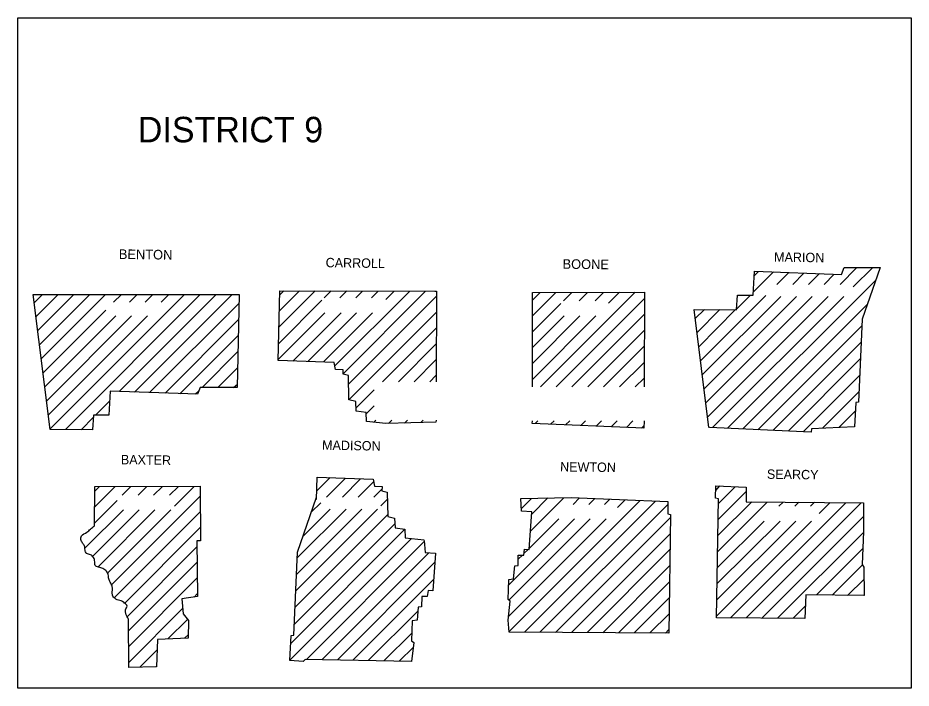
# Model space of a CAD drawing. Extents: x 23481 to 28196, y 1325020 to 1327623.
# Drawn here: x 27385.4 to 27785.4, y 1325389.9 to 1325689.9 of the extents above; entities that cross this region are included whole.
import ezdxf

# ---------------------------------------------------------------- set-up
doc = ezdxf.new("R2010")
doc.units = 0
doc.layers.add('S_ELECTRIC_UTILITIES_ANNOT', color=7, linetype='Continuous')

msp = doc.modelspace()

# ---------------------------------------------------------------- linework, layer by layer
at = {"layer": 'S_ELECTRIC_UTILITIES_ANNOT'}
msp.add_lwpolyline([(27385.36, 1325389.92), (27385.36, 1325689.92), (27785.36, 1325689.92), (27785.36, 1325389.92)], close=True, dxfattribs=at)
for points in [[(27688.46, 1325559.32), (27707.16, 1325559.22), (27707.66, 1325565.82), (27714.56, 1325565.82), (27715.16, 1325576.52), (27754.16, 1325575.12), (27755.36, 1325578.12), (27771.46, 1325578.22), (27763.36, 1325555.02), (27761.76, 1325517.92), (27760.56, 1325517.82), (27759.96, 1325506.92)], [(27714.66, 1325567.12), (27723.66, 1325576.22)], [(27715.06, 1325574.52), (27716.96, 1325576.42)], [(27753.56, 1325570.62), (27761.06, 1325578.12)], [(27759.46, 1325569.52), (27768.16, 1325578.12)], [(27703.16, 1325506.22), (27769.36, 1325572.32)], [(27725.26, 1325570.62), (27730.56, 1325575.92)], [(27732.36, 1325570.62), (27737.36, 1325575.72)], [(27739.36, 1325570.62), (27744.26, 1325575.52)], [(27746.46, 1325570.62), (27750.96, 1325575.22)], [(27399.76, 1325505.62), (27392.16, 1325566.12)], [(27392.16, 1325566.12), (27484.46, 1325566.12)], [(27392.66, 1325562.42), (27396.46, 1325566.12)], [(27393.46, 1325556.12), (27403.46, 1325566.12)], [(27394.26, 1325549.92), (27410.46, 1325566.12)], [(27395.06, 1325543.62), (27417.56, 1325566.12)], [(27395.86, 1325537.32), (27424.66, 1325566.12)], [(27399.86, 1325505.92), (27459.96, 1325566.12)], [(27406.66, 1325505.62), (27467.06, 1325566.12)], [(27428.26, 1325562.62), (27431.76, 1325566.12)], [(27430.76, 1325522.62), (27474.16, 1325566.12)], [(27435.36, 1325562.62), (27438.76, 1325566.12)], [(27437.56, 1325522.42), (27481.26, 1325566.12)], [(27442.36, 1325562.62), (27445.86, 1325566.12)], [(27449.46, 1325562.62), (27452.96, 1325566.12)], [(27484.46, 1325566.12), (27483.56, 1325524.52)], [(27501.96, 1325536.52), (27502.66, 1325567.72)], [(27502.26, 1325551.42), (27518.56, 1325567.72)], [(27502.46, 1325558.72), (27511.46, 1325567.72)], [(27502.66, 1325565.92), (27504.46, 1325567.72)], [(27502.66, 1325567.72), (27572.06, 1325567.62), (27572.76, 1325567.62)], [(27522.56, 1325564.62), (27525.66, 1325567.72)], [(27527.36, 1325534.12), (27560.86, 1325567.62)], [(27529.56, 1325564.62), (27532.66, 1325567.72)], [(27530.96, 1325530.62), (27567.96, 1325567.62)], [(27533.46, 1325526.02), (27572.76, 1325565.32)], [(27536.76, 1325564.62), (27539.66, 1325567.62)], [(27543.76, 1325564.62), (27546.76, 1325567.62)], [(27550.16, 1325563.92), (27553.86, 1325567.62)], [(27572.76, 1325567.62), (27572.66, 1325527.02)], [(27615.76, 1325563.52), (27619.26, 1325567.02)], [(27615.76, 1325524.72), (27615.86, 1325567.02)], [(27615.86, 1325567.02), (27665.96, 1325567.22)], [(27615.86, 1325556.52), (27626.26, 1325567.02)], [(27619.36, 1325524.72), (27661.76, 1325567.12)], [(27626.46, 1325524.72), (27665.86, 1325564.12)], [(27629.76, 1325563.32), (27633.46, 1325567.02)], [(27636.76, 1325563.32), (27640.46, 1325567.02)], [(27643.86, 1325563.32), (27647.56, 1325567.02)], [(27649.86, 1325562.22), (27654.76, 1325567.12)], [(27665.96, 1325567.22), (27665.76, 1325524.72)], [(27691.06, 1325536.42), (27720.36, 1325565.72)], [(27691.86, 1325530.12), (27726.96, 1325565.22)], [(27692.66, 1325523.92), (27733.96, 1325565.22)], [(27693.46, 1325517.62), (27741.06, 1325565.22)], [(27694.26, 1325511.32), (27748.16, 1325565.22)], [(27696.46, 1325506.52), (27755.26, 1325565.22)], [(27707.26, 1325559.72), (27713.36, 1325565.82)], [(27444.36, 1325522.22), (27484.36, 1325562.12)], [(27502.16, 1325544.22), (27521.46, 1325563.52)], [(27615.86, 1325549.42), (27628.46, 1325562.02)], [(27709.96, 1325505.92), (27765.56, 1325561.52)], [(27396.66, 1325531.02), (27424.76, 1325559.12)], [(27397.46, 1325524.72), (27429.26, 1325556.52)], [(27398.26, 1325518.52), (27436.26, 1325556.52)], [(27399.06, 1325512.22), (27443.36, 1325556.52)], [(27501.96, 1325537.02), (27522.86, 1325557.92)], [(27508.46, 1325536.32), (27530.06, 1325557.92)], [(27515.26, 1325536.12), (27537.06, 1325557.92)], [(27522.16, 1325535.92), (27544.16, 1325557.92)], [(27533.56, 1325519.02), (27572.76, 1325558.22)], [(27615.76, 1325528.12), (27644.16, 1325556.52)], [(27615.76, 1325535.22), (27637.06, 1325556.52)], [(27615.86, 1325542.42), (27629.96, 1325556.52)], [(27633.46, 1325524.72), (27665.86, 1325557.12)], [(27694.76, 1325506.52), (27688.16, 1325559.32)], [(27688.66, 1325555.32), (27692.76, 1325559.32)], [(27689.46, 1325549.02), (27699.76, 1325559.32)], [(27690.26, 1325542.72), (27706.76, 1325559.32)], [(27451.26, 1325521.92), (27484.16, 1325554.92)], [(27716.66, 1325505.52), (27763.26, 1325552.02)], [(27548.66, 1325527.02), (27572.66, 1325551.02)], [(27640.66, 1325524.72), (27665.86, 1325549.92)], [(27457.96, 1325521.62), (27484.06, 1325547.72)], [(27555.76, 1325527.02), (27572.66, 1325544.02)], [(27723.46, 1325505.22), (27762.86, 1325544.62)], [(27467.86, 1325524.42), (27483.86, 1325540.52)], [(27647.66, 1325524.72), (27665.86, 1325542.92)], [(27572.66, 1325509.92), (27572.56, 1325508.92), (27550.16, 1325508.42), (27541.46, 1325509.32), (27541.26, 1325513.32), (27536.86, 1325513.92), (27536.66, 1325518.22), (27533.56, 1325518.92), (27533.36, 1325529.82), (27530.96, 1325530.42), (27531.06, 1325532.42), (27527.66, 1325532.52), (27527.06, 1325535.72), (27501.96, 1325536.52)], [(27562.76, 1325527.02), (27572.56, 1325536.82)], [(27730.26, 1325504.92), (27762.56, 1325537.32)], [(27474.96, 1325524.42), (27483.76, 1325533.32)], [(27654.76, 1325524.72), (27665.76, 1325535.72)], [(27569.86, 1325527.02), (27572.56, 1325529.82)], [(27661.86, 1325524.72), (27665.76, 1325528.62)], [(27736.96, 1325504.62), (27762.26, 1325529.82)], [(27483.56, 1325524.52), (27466.96, 1325524.42), (27465.76, 1325521.42), (27426.76, 1325522.82), (27426.16, 1325512.12), (27419.26, 1325512.12), (27418.76, 1325505.52), (27399.76, 1325505.62)], [(27481.96, 1325524.42), (27483.66, 1325526.02)], [(27464.76, 1325521.42), (27466.46, 1325523.02)], [(27536.86, 1325515.32), (27544.96, 1325523.42)], [(27745.66, 1325506.22), (27761.86, 1325522.42)], [(27420.16, 1325512.12), (27426.56, 1325518.52)], [(27541.36, 1325512.62), (27544.96, 1325516.32)], [(27753.16, 1325506.72), (27760.36, 1325513.82)], [(27413.66, 1325505.52), (27419.26, 1325511.22)], [(27544.76, 1325509.02), (27545.66, 1325509.92)], [(27551.26, 1325508.42), (27552.76, 1325509.92)], [(27558.46, 1325508.52), (27559.86, 1325509.92)], [(27565.76, 1325508.82), (27566.86, 1325509.92)], [(27615.66, 1325508.32), (27615.76, 1325509.52)], [(27665.66, 1325506.22), (27615.66, 1325508.32)], [(27617.06, 1325508.32), (27618.26, 1325509.52)], [(27623.86, 1325508.02), (27625.46, 1325509.52)], [(27630.66, 1325507.72), (27632.46, 1325509.52)], [(27637.46, 1325507.42), (27639.56, 1325509.52)], [(27644.26, 1325507.12), (27646.66, 1325509.52)], [(27651.06, 1325506.92), (27653.66, 1325509.52)], [(27657.86, 1325506.62), (27660.76, 1325509.52)], [(27665.76, 1325509.52), (27665.66, 1325506.22)], [(27664.66, 1325506.32), (27665.76, 1325507.42)], [(27759.96, 1325506.92), (27740.76, 1325506.02), (27740.56, 1325504.42), (27695.06, 1325506.52)], [(27519.16, 1325474.42), (27519.36, 1325484.32)], [(27519.16, 1325478.12), (27525.16, 1325484.12)], [(27519.36, 1325484.32), (27544.46, 1325483.52), (27545.06, 1325480.32), (27548.46, 1325480.22), (27548.36, 1325478.22), (27550.76, 1325477.62), (27550.96, 1325466.72), (27554.06, 1325466.02), (27554.26, 1325461.72), (27558.66, 1325461.12), (27558.86, 1325457.12), (27567.36, 1325456.22)], [(27419.66, 1325462.62), (27419.86, 1325480.22)], [(27419.76, 1325471.02), (27428.86, 1325480.12)], [(27419.76, 1325478.12), (27421.86, 1325480.12)], [(27419.86, 1325480.22), (27466.96, 1325480.32)], [(27432.06, 1325476.22), (27435.96, 1325480.12)], [(27466.96, 1325480.32), (27467.16, 1325455.92), (27465.46, 1325455.82), (27465.76, 1325430.92), (27458.76, 1325429.92), (27459.36, 1325423.22), (27461.76, 1325420.12), (27461.56, 1325412.22), (27447.96, 1325411.72), (27447.46, 1325399.52), (27435.06, 1325399.12)], [(27439.16, 1325476.22), (27443.06, 1325480.12)], [(27446.16, 1325476.22), (27450.16, 1325480.22)], [(27453.26, 1325476.22), (27457.26, 1325480.22)], [(27455.46, 1325471.32), (27464.36, 1325480.22)], [(27523.56, 1325475.42), (27531.96, 1325483.82)], [(27530.66, 1325475.42), (27538.86, 1325483.62)], [(27537.76, 1325475.42), (27544.66, 1325482.32)], [(27698.26, 1325421.42), (27699.06, 1325474.62), (27697.76, 1325474.92), (27697.86, 1325480.42)], [(27697.86, 1325480.42), (27711.56, 1325479.82), (27711.46, 1325473.32), (27763.96, 1325472.92)], [(27697.86, 1325478.42), (27699.76, 1325480.42)], [(27699.06, 1325472.52), (27706.56, 1325480.02)], [(27544.76, 1325475.42), (27548.36, 1325479.02)], [(27698.96, 1325465.42), (27711.46, 1325477.92)], [(27419.76, 1325463.92), (27429.76, 1325473.92)], [(27427.36, 1325436.22), (27466.96, 1325475.82)], [(27561.66, 1325401.82), (27513.96, 1325402.72), (27513.06, 1325401.82), (27507.16, 1325402.32), (27507.76, 1325413.52), (27508.96, 1325413.62), (27510.56, 1325450.72), (27519.16, 1325475.42)], [(27516.76, 1325468.62), (27521.06, 1325472.92)], [(27547.86, 1325471.52), (27550.76, 1325474.42)], [(27604.86, 1325420.32), (27605.86, 1325428.82), (27604.86, 1325429.52), (27605.16, 1325438.52), (27607.36, 1325438.82), (27607.86, 1325444.72), (27609.36, 1325444.82), (27609.46, 1325449.42), (27611.86, 1325449.42), (27612.26, 1325452.12), (27614.36, 1325452.02), (27615.56, 1325468.82), (27610.96, 1325469.12), (27610.56, 1325474.72)], [(27605.36, 1325415.32), (27664.06, 1325473.92)], [(27610.56, 1325474.72), (27610.76, 1325474.72), (27633.16, 1325475.22)], [(27610.96, 1325470.32), (27615.36, 1325474.72)], [(27612.16, 1325415.02), (27670.86, 1325473.62)], [(27614.96, 1325460.22), (27629.86, 1325475.12)], [(27615.46, 1325467.72), (27622.66, 1325475.02)], [(27619.16, 1325414.92), (27676.36, 1325472.12)], [(27633.16, 1325475.22), (27676.46, 1325473.42)], [(27633.96, 1325472.12), (27636.86, 1325475.02)], [(27641.06, 1325472.12), (27643.66, 1325474.72)], [(27648.06, 1325472.12), (27650.46, 1325474.52)], [(27653.86, 1325470.82), (27657.26, 1325474.22)], [(27676.46, 1325473.42), (27676.36, 1325467.92), (27677.66, 1325467.62), (27676.86, 1325414.52)], [(27698.76, 1325451.02), (27720.96, 1325473.22)], [(27698.86, 1325458.22), (27713.96, 1325473.32)], [(27704.46, 1325421.42), (27756.06, 1325472.92)], [(27711.46, 1325421.32), (27763.06, 1325472.92)], [(27726.16, 1325471.32), (27728.06, 1325473.22)], [(27733.26, 1325471.32), (27735.06, 1325473.12)], [(27740.26, 1325471.32), (27742.06, 1325473.12)], [(27744.16, 1325468.12), (27749.06, 1325473.02)], [(27763.96, 1325472.92), (27764.06, 1325460.02)], [(27415.36, 1325452.52), (27432.66, 1325469.72)], [(27418.96, 1325449.02), (27439.66, 1325469.72)], [(27421.16, 1325444.12), (27446.76, 1325469.72)], [(27425.66, 1325441.52), (27453.86, 1325469.72)], [(27428.66, 1325430.42), (27467.06, 1325468.82)], [(27509.86, 1325433.42), (27546.46, 1325470.02)], [(27510.16, 1325440.82), (27539.36, 1325470.02)], [(27510.46, 1325448.22), (27532.36, 1325470.02)], [(27513.06, 1325457.92), (27525.26, 1325470.02)], [(27509.56, 1325426.12), (27550.86, 1325467.42)], [(27605.16, 1325422.12), (27648.76, 1325465.72)], [(27605.16, 1325436.22), (27634.66, 1325465.72)], [(27605.26, 1325429.32), (27641.66, 1325465.72)], [(27614.46, 1325452.62), (27627.56, 1325465.72)], [(27626.16, 1325414.82), (27677.56, 1325466.32)], [(27698.36, 1325422.32), (27740.76, 1325464.72)], [(27698.36, 1325429.42), (27733.66, 1325464.72)], [(27698.56, 1325436.72), (27726.66, 1325464.72)], [(27698.56, 1325443.82), (27719.56, 1325464.72)], [(27718.46, 1325421.22), (27763.96, 1325466.72)], [(27433.26, 1325428.02), (27467.06, 1325461.82)], [(27507.56, 1325409.92), (27558.66, 1325461.02)], [(27509.26, 1325418.62), (27554.16, 1325463.52)], [(27764.06, 1325460.02), (27763.46, 1325445.22), (27764.16, 1325444.02), (27764.36, 1325431.32)], [(27507.26, 1325402.52), (27561.46, 1325456.72)], [(27567.36, 1325456.02), (27567.76, 1325450.62), (27572.36, 1325450.32), (27571.16, 1325433.52), (27569.06, 1325433.62), (27568.66, 1325430.92), (27566.26, 1325430.92), (27566.16, 1325426.32), (27564.66, 1325426.22), (27564.16, 1325420.32), (27561.96, 1325420.02), (27561.66, 1325411.02), (27562.66, 1325410.32), (27561.66, 1325401.82)], [(27633.26, 1325414.82), (27677.56, 1325459.12)], [(27725.56, 1325421.22), (27763.96, 1325459.62)], [(27434.46, 1325422.02), (27465.46, 1325453.12)], [(27514.56, 1325402.72), (27567.36, 1325455.52)], [(27611.96, 1325450.12), (27613.86, 1325452.02)], [(27742.96, 1325431.62), (27763.76, 1325452.42)], [(27521.46, 1325402.62), (27569.36, 1325450.52)], [(27609.46, 1325447.62), (27611.26, 1325449.42)], [(27640.26, 1325414.82), (27677.36, 1325451.92)], [(27434.96, 1325415.52), (27465.56, 1325446.12)], [(27528.46, 1325402.52), (27571.96, 1325446.12)], [(27647.26, 1325414.72), (27677.36, 1325444.82)], [(27749.96, 1325431.52), (27763.56, 1325445.12)], [(27435.06, 1325408.52), (27465.56, 1325439.12)], [(27535.36, 1325402.42), (27571.46, 1325438.52)], [(27654.36, 1325414.72), (27677.16, 1325437.52)], [(27756.86, 1325431.42), (27764.26, 1325438.72)], [(27464.26, 1325430.62), (27465.66, 1325432.12)], [(27661.36, 1325414.62), (27677.16, 1325430.42)], [(27764.36, 1325431.32), (27738.26, 1325431.62), (27737.76, 1325421.12), (27698.26, 1325421.42)], [(27763.96, 1325431.42), (27764.26, 1325431.72)], [(27435.06, 1325401.42), (27459.06, 1325425.52)], [(27542.26, 1325402.22), (27564.46, 1325424.42)], [(27732.56, 1325421.22), (27738.06, 1325426.72)], [(27435.06, 1325399.12), (27434.96, 1325420.82)], [(27452.56, 1325411.92), (27461.26, 1325420.62)], [(27605.36, 1325415.02), (27604.86, 1325420.32)], [(27668.36, 1325414.62), (27676.96, 1325423.22)], [(27675.36, 1325414.52), (27676.86, 1325416.12)], [(27459.96, 1325412.22), (27461.56, 1325413.82)], [(27549.26, 1325402.12), (27561.86, 1325414.72)], [(27676.86, 1325414.52), (27605.36, 1325415.02)], [(27556.16, 1325401.92), (27562.46, 1325408.22)], [(27439.96, 1325399.32), (27447.76, 1325407.12)], [(27447.26, 1325399.52), (27447.46, 1325399.72)]]:
    msp.add_lwpolyline(points, dxfattribs=at)
msp.add_spline([(27434.96, 1325420.82), (27433.66, 1325423.42), (27433.56, 1325424.92), (27434.26, 1325426.62), (27433.16, 1325428.02), (27431.56, 1325429.02), (27429.26, 1325429.72), (27427.96, 1325431.12), (27427.56, 1325432.52), (27427.76, 1325434.02), (27427.56, 1325435.52), (27426.76, 1325437.32), (27426.06, 1325438.82), (27425.86, 1325440.72), (27425.06, 1325442.22), (27423.36, 1325443.42), (27421.56, 1325444.02), (27419.96, 1325444.82), (27419.76, 1325446.52), (27419.26, 1325448.32), (27417.86, 1325449.62), (27416.16, 1325450.22), (27415.46, 1325451.72), (27415.16, 1325453.52), (27414.36, 1325454.82), (27413.56, 1325456.42), (27413.86, 1325458.02), (27416.26, 1325459.72), (27417.86, 1325461.12), (27419.66, 1325462.62)], degree=3, dxfattribs=at)

# ---------------------------------------------------------------- texts
msp.add_text('DISTRICT 9', height=11.4, dxfattribs=at).set_placement((27439.06, 1325634.22))
for s, height, rotation, p in [('BENTON', 4.301, 359.2527, (27430.56, 1325582.02)), ('MARION', 4.201, 359.1854, (27723.96, 1325580.82)), ('CARROLL', 4.201, 359.1481, (27523.16, 1325578.32)), ('BOONE', 4.301, 359.4001, (27629.26, 1325577.62)), ('MADISON', 4.201, 359.0906, (27521.56, 1325496.62)), ('BAXTER', 4.201, 359.2559, (27431.46, 1325490.12)), ('NEWTON', 4.201, 359.2717, (27628.16, 1325486.92)), ('SEARCY', 4.199, 359.2527, (27720.76, 1325483.62))]:
    msp.add_text(s, height=height, rotation=rotation, dxfattribs=at).set_placement(p)

doc.saveas('drawing.dxf')
